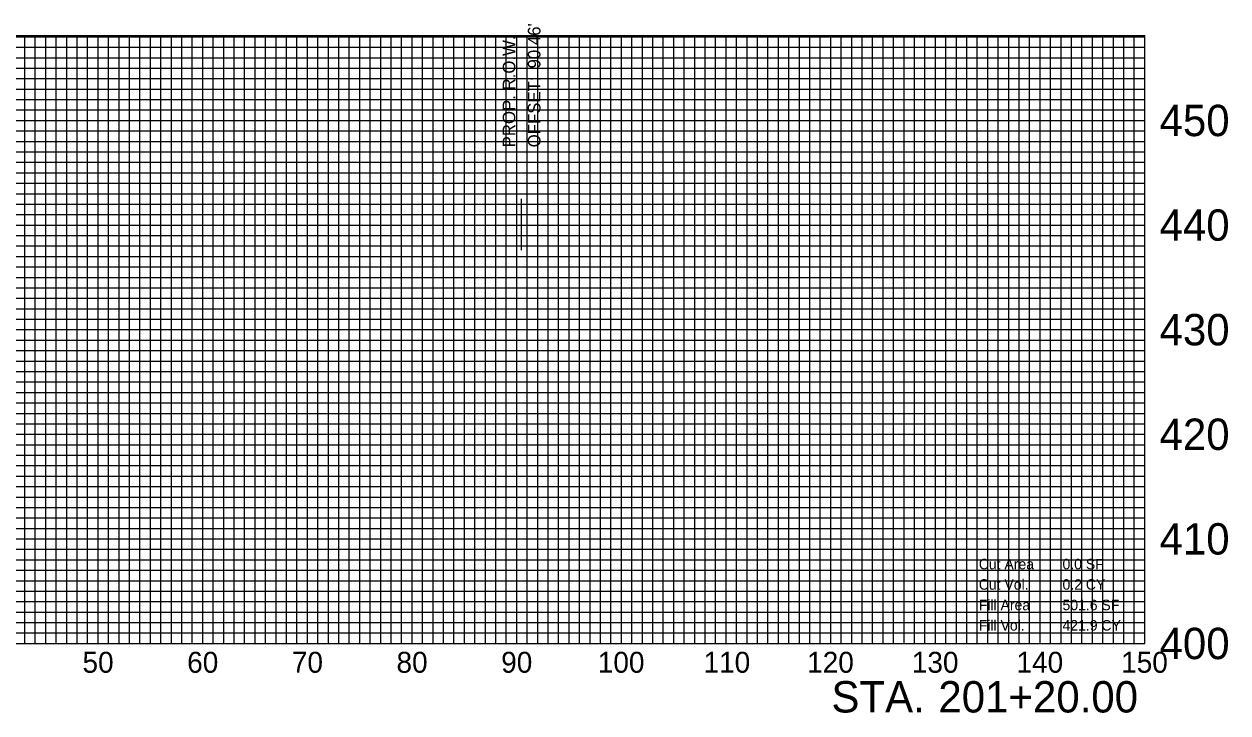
# Model space of a CAD drawing. Extents: x -158 to 158, y 393 to 462.
# Drawn here: x 42.9 to 157.9, y 393.4 to 459.2 of the extents above; entities that cross this region are included whole.
import ezdxf

# ---------------------------------------------------------------- set-up
doc = ezdxf.new("R2010")
doc.units = 0
for name, color, linetype in [('DES - MODEL - Lines - Cut Slopes', 7, 'Continuous'), ('DES - MODEL - Lines - Ditch Centerline', 7, 'Continuous'), ('DES - MODEL - Lines - Draft DNC', 7, 'Continuous'), ('SUR - DTM - Breaklines', 7, 'Continuous'), ('SUR - DTM - Contours - Major', 7, 'Continuous'), ('SUR - DTM - Graphic Voids', 7, 'Continuous')]:
    doc.layers.add(name, color=color, linetype=linetype)

msp = doc.modelspace()

# ---------------------------------------------------------------- linework, layer by layer
at = {"layer": 'DES - MODEL - Lines - Ditch Centerline'}
msp.add_line((90.46, 437.59), (90.46, 442.51), dxfattribs=at)
msp.add_line((90.46, 437.59), (90.46, 442.51), dxfattribs=at)
msp.add_line((90.46, 437.59), (90.46, 442.51), dxfattribs=at)
at = {"layer": 'SUR - DTM - Breaklines'}
for p, q in [((-150, 458), (150, 458)), ((43, 400), (43, 458.11)), ((44, 400), (44, 458.11)), ((45, 400), (45, 458.11)), ((46, 400), (46, 458.11)), ((47, 400), (47, 458.11)), ((48, 400), (48, 458.11)), ((49, 400), (49, 458.11)), ((51, 400), (51, 458.11)), ((52, 400), (52, 458.11)), ((53, 400), (53, 458.11)), ((54, 400), (54, 458.11)), ((55, 400), (55, 458.11)), ((56, 400), (56, 458.11)), ((57, 400), (57, 458.11)), ((58, 400), (58, 458.11)), ((59, 400), (59, 458.11)), ((61, 400), (61, 458.11)), ((62, 400), (62, 458.11)), ((63, 400), (63, 458.11)), ((64, 400), (64, 458.11)), ((65, 400), (65, 458.11)), ((66, 400), (66, 458.11)), ((67, 400), (67, 458.11)), ((68, 400), (68, 458.11)), ((69, 400), (69, 458.11)), ((71, 400), (71, 458.11)), ((72, 400), (72, 458.11)), ((73, 400), (73, 458.11)), ((74, 400), (74, 458.11)), ((75, 400), (75, 458.11)), ((76, 400), (76, 458.11)), ((77, 400), (77, 458.11)), ((78, 400), (78, 458.11)), ((79, 400), (79, 458.11)), ((81, 400), (81, 458.11)), ((82, 400), (82, 458.11)), ((83, 400), (83, 458.11)), ((84, 400), (84, 458.11)), ((85, 400), (85, 458.11)), ((86, 400), (86, 458.11)), ((87, 400), (87, 458.11)), ((88, 400), (88, 458.11)), ((89, 400), (89, 458.11)), ((91, 400), (91, 458.11)), ((92, 400), (92, 458.11)), ((93, 400), (93, 458.11)), ((94, 400), (94, 458.11)), ((95, 400), (95, 458.11)), ((96, 400), (96, 458.11)), ((97, 400), (97, 458.11)), ((98, 400), (98, 458.11)), ((99, 400), (99, 458.11)), ((101, 400), (101, 458.11)), ((102, 400), (102, 458.11)), ((103, 400), (103, 458.11)), ((104, 400), (104, 458.11)), ((105, 400), (105, 458.11)), ((106, 400), (106, 458.11)), ((107, 400), (107, 458.11)), ((108, 400), (108, 458.11)), ((109, 400), (109, 458.11)), ((111, 400), (111, 458.11)), ((112, 400), (112, 458.11)), ((113, 400), (113, 458.11)), ((114, 400), (114, 458.11)), ((115, 400), (115, 458.11)), ((116, 400), (116, 458.11)), ((117, 400), (117, 458.11)), ((118, 400), (118, 458.11)), ((119, 400), (119, 458.11)), ((121, 400), (121, 458.11)), ((122, 400), (122, 458.11)), ((123, 400), (123, 458.11)), ((124, 400), (124, 458.11)), ((125, 400), (125, 458.11)), ((126, 400), (126, 458.11)), ((127, 400), (127, 458.11)), ((128, 400), (128, 458.11)), ((129, 400), (129, 458.11)), ((131, 400), (131, 458.11)), ((132, 400), (132, 458.11)), ((133, 400), (133, 458.11)), ((134, 400), (134, 458.11)), ((135, 400), (135, 458.11)), ((136, 400), (136, 458.11)), ((137, 400), (137, 458.11)), ((138, 400), (138, 458.11)), ((139, 400), (139, 458.11)), ((141, 400), (141, 458.11)), ((142, 400), (142, 458.11)), ((143, 400), (143, 458.11)), ((144, 400), (144, 458.11)), ((145, 400), (145, 458.11)), ((146, 400), (146, 458.11)), ((147, 400), (147, 458.11)), ((148, 400), (148, 458.11)), ((149, 400), (149, 458.11)), ((-150, 457), (150, 457)), ((-150, 456), (150, 456)), ((-150, 455), (150, 455)), ((-150, 454), (150, 454)), ((-150, 453), (150, 453)), ((-150, 452), (150, 452)), ((-150, 451), (150, 451)), ((-150, 449), (150, 449)), ((-150, 448), (150, 448)), ((-150, 447), (150, 447)), ((-150, 446), (150, 446)), ((-150, 445), (150, 445)), ((-150, 444), (150, 444)), ((-150, 443), (150, 443)), ((-150, 442), (150, 442)), ((-150, 441), (150, 441)), ((-150, 439), (150, 439)), ((-150, 438), (150, 438)), ((-150, 437), (150, 437)), ((-150, 436), (150, 436)), ((-150, 435), (150, 435)), ((-150, 434), (150, 434)), ((-150, 433), (150, 433)), ((-150, 432), (150, 432)), ((-150, 431), (150, 431)), ((-150, 429), (150, 429)), ((-150, 428), (150, 428)), ((-150, 427), (150, 427)), ((-150, 426), (150, 426)), ((-150, 425), (150, 425)), ((-150, 424), (150, 424)), ((-150, 423), (150, 423)), ((-150, 422), (150, 422)), ((-150, 421), (150, 421)), ((-150, 419), (150, 419)), ((-150, 418), (150, 418)), ((-150, 417), (150, 417)), ((-150, 416), (150, 416)), ((-150, 415), (150, 415)), ((-150, 414), (150, 414)), ((-150, 413), (150, 413)), ((-150, 412), (150, 412)), ((-150, 411), (150, 411)), ((-150, 409), (150, 409)), ((-150, 408), (150, 408)), ((-150, 407), (150, 407)), ((-150, 406), (150, 406)), ((-150, 405), (150, 405)), ((-150, 404), (150, 404)), ((-150, 403), (150, 403)), ((-150, 402), (150, 402)), ((-150, 401), (150, 401))]:
    msp.add_line(p, q, dxfattribs=at)
at = {"layer": 'SUR - DTM - Contours - Major'}
for p, q in [((-150, 458.11), (150, 458.11)), ((50, 400), (50, 458.11)), ((60, 400), (60, 458.11)), ((70, 400), (70, 458.11)), ((80, 400), (80, 458.11)), ((90, 400), (90, 458.11)), ((100, 400), (100, 458.11)), ((110, 400), (110, 458.11)), ((120, 400), (120, 458.11)), ((130, 400), (130, 458.11)), ((140, 400), (140, 458.11)), ((150, 400), (150, 458.11)), ((-150, 450), (150, 450)), ((-150, 440), (150, 440)), ((-150, 430), (150, 430)), ((-150, 420), (150, 420)), ((-150, 410), (150, 410)), ((-150, 400), (150, 400))]:
    msp.add_line(p, q, dxfattribs=at)

# ---------------------------------------------------------------- texts
at = {"layer": 'DES - MODEL - Lines - Cut Slopes'}
for s, p in [('Fill Area', (134.14, 403.18)), ('501.6 SF', (142.14, 403.18)), ('Fill Vol.', (134.14, 401.23)), ('421.9 CY', (142.14, 401.23))]:
    msp.add_text(s, height=1, dxfattribs=at).set_placement(p)
at = {"layer": 'DES - MODEL - Lines - Ditch Centerline'}
for s, p in [("90.46'", (92.26, 454.97)), ("90.46'", (92.26, 454.97)), ("90.46'", (92.26, 454.97)), ('PROP. R.O.W.', (89.86, 447.43)), ('PROP. R.O.W.', (89.86, 447.43)), ('PROP. R.O.W.', (89.86, 447.43)), ('OFFSET: ', (92.26, 447.43)), ('OFFSET: ', (92.26, 447.43)), ('OFFSET: ', (92.26, 447.43))]:
    msp.add_text(s, height=1.2, rotation=90, dxfattribs=at).set_placement(p)
at = {"layer": 'DES - MODEL - Lines - Draft DNC'}
for s, p in [('Cut Area', (134.14, 407.09)), ('0.0 SF', (142.14, 407.09)), ('Cut Vol.', (134.14, 405.14)), ('0.2 CY', (142.14, 405.14))]:
    msp.add_text(s, height=1, dxfattribs=at).set_placement(p)
at = {"layer": 'SUR - DTM - Graphic Voids'}
for s, height, p in [('450', 3, (151.41, 448.5)), ('440', 3, (151.41, 438.5)), ('430', 3, (151.41, 428.5)), ('420', 3, (151.41, 418.5)), ('410', 3, (151.41, 408.5)), ('400', 3, (151.41, 398.5)), ('50', 2, (48.51, 397.2)), ('60', 2, (58.51, 397.2)), ('70', 2, (68.51, 397.2)), ('80', 2, (78.51, 397.2)), ('90', 2, (88.51, 397.2)), ('100', 2, (97.74, 397.2)), ('110', 2, (107.84, 397.2)), ('120', 2, (117.74, 397.2)), ('130', 2, (127.74, 397.2)), ('140', 2, (137.74, 397.2)), ('150', 2, (147.74, 397.2)), (' STA. ', 3, (118.95, 393.4)), ('201+20.00', 3, (130.28, 393.4))]:
    msp.add_text(s, height=height, dxfattribs=at).set_placement(p)

doc.saveas('drawing.dxf')
